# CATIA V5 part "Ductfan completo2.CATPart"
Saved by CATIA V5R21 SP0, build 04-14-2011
Part number: Ductfan2
Bounding box of the stored display mesh (mm): x -394.667 to 344.98, y -40 to 360, z -344.802 to 344.802
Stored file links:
  C:\Users\rodri\OneDrive\Área de Trabalho\FACULDADE\3°semestre\Sistemas Aeroespaciais\Projeto de avião 2019-02\CAD\Ductfan completo2.CATPart
  C:\Users\andre\AppData\Local\Temp\Rar$DIa18808.12376\NACA 2412 3D Aerofoil.CATPart
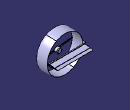
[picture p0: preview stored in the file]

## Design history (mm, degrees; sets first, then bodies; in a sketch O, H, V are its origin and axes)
Body1 (main body)
  Sketch1 on yz-plane, origin (0, 0, 0), H (0, 1, 0), V (0, 0, 1)
    point P1 (-40, -336.52)
    point P2 (160, -336.52)
    unspec C1
    unspec C2
    axis line L1 (0, -34.7251) -> (0, -104.5277)
    distance P1 P2 = 200
    distance C1 C2 = 23.9924
    distance P1 L1 = 40
    distance C1 H = 320.675
    distance P2 H = 336.52
    vertical: L1 V
    coincidence: L1 V
  Shaft1: profile Sketch1, axis Sketch1.H, angle 360
  Sketch2 on zx-plane, origin (0, 0, 0), H (-1, 0, 0), V (0, 0, 1)
    circle A1 centre (0, 0) radius 45.8
    radius A1 = 45.8
  Pad1: profile Sketch2, direction (0, 1, 0), length 60
  Fillet1: radius 10, on edge [face of Pad1 from Sketch2.A1 | end face of Pad1]
  Sketch3 on start face of Pad1, origin (0, 0, 0), H (1, 0, 0), V (0, 0, 1)
    circle A1 centre (0, 0) radius 10
    point P1 (10, 0)
    radius A1 = 10
    coincidence: A1 P1, P1 H
  Pocket1: profile Sketch3, direction (0, 1, 0), length 10
  Sketch4 on start face of Pad1, origin (0, 0, 0), H (1, 0, 0), V (0, 0, 1)
    ellipse A1 centre (0, 0) semi-axes 306.75, 10 rotation 172.047
    "Radius" A1 = 306.75
    distance A1 O = 10
  Pad2: profile Sketch4, direction (0, -1, 0), length 10
  Plane1: type Offset, RefPlane yz-plane, Offset 344.667, reversed
  Sketch5 on Plane1, origin (-344.667, 0, 0), H (0, 1, 0), V (0, 0, 1)
    point P1 (-40, -2.4533)
    point P2 (160, -2.4533)
    unspec C1
    unspec C2
    circle A1 centre (0, 0) radius 5
    point P3 (0, 0)
    circle A2 centre (60.03, -0.0038) radius 5
    point P4 (60.03, -0.0038)
    distance P1 P2 = 200
    distance P1 V = 40
    radius A1 = 5
    distance C1 C2 = 23.9924
    distance P3 C1 = 11.996
    distance P3 P1 = 40.0752
    radius A2 = 5
    distance P4 P2 = 100
    distance P4 C1 = 11.996
    distance P3 H = 0
    coincidence: P3 V
  Pad3: profile Sketch5, direction (-1, 0, 0), length 50
  Sketch6 on yz-plane, origin (0, 0, 0), H (0, 1, 0), V (0, 0, 1)
    point P1 (160, -0.1822)
    unspec C1
    unspec C2
    point P3 (26.5548, 0)
    point P4 (180, 2)
    circle A1 centre (180, 2) radius 5
    point P5 (184.5826, 0)
    line L1 (190, 11) -> (196, 11)
    line L2 (196, 11) -> (196, -6)
    line L3 (196, -6) -> (190, -6)
    line L4 (190, -6) -> (190, 11)
    point P10 (210, 3)
    circle A2 centre (210, 3) radius 7.5
    point P11 (235, 4)
    circle A3 centre (235, 4) radius 7.5
    point P12 (260, 4)
    circle A4 centre (260, 4) radius 7.5
    point P13 (285, 3)
    circle A5 centre (285, 3) radius 5
    line L5 (300, 8) -> (304, 8)
    line L6 (304, 8) -> (304, -2)
    line L7 (304, -2) -> (300, -2)
    line L8 (300, -2) -> (300, 8)
    radius A1 = 5
    distance H P4 = 2
    distance V P4 = 180
    distance L4 L2 = 6
    distance L1 L3 = 17
    distance L3 H = 6
    distance L4 V = 190
    radius A2 = 7.5
    distance P10 H = 3
    distance P10 V = 210
    radius A3 = 7.5
    distance P11 H = 4
    radius A4 = 7.5
    distance P11 V = 235
    distance P12 H = 4
    distance P12 V = 260
    radius A5 = 5
    distance P13 H = 3
    distance P13 V = 285
    distance L5 L7 = 10
    distance L8 L6 = 4
    distance L8 V = 300
    distance L7 H = 2
    distance P1 V = 160
    coincidence: A1 P5, P5 H
    horizontal: L1 H, L3 H, L5 H, L7 H
    vertical: L2 V, L4 V, L6 V, L8 V
  Pad4: profile Sketch6, direction (1, 0, 0), length 336.52, mirrored extent
  Sketch7 on end face of Pad4, origin (336.52, 0, 0), H (0, 1, 0), V (0, 0, 1)
    point P2 (360, 0)
    unspec C1
    unspec C2
    distance P2 V = 360
  Pad5: profile Sketch7, direction (1, 0, 0), length 5
  Fillet2: radius 2, on end face of Pad5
